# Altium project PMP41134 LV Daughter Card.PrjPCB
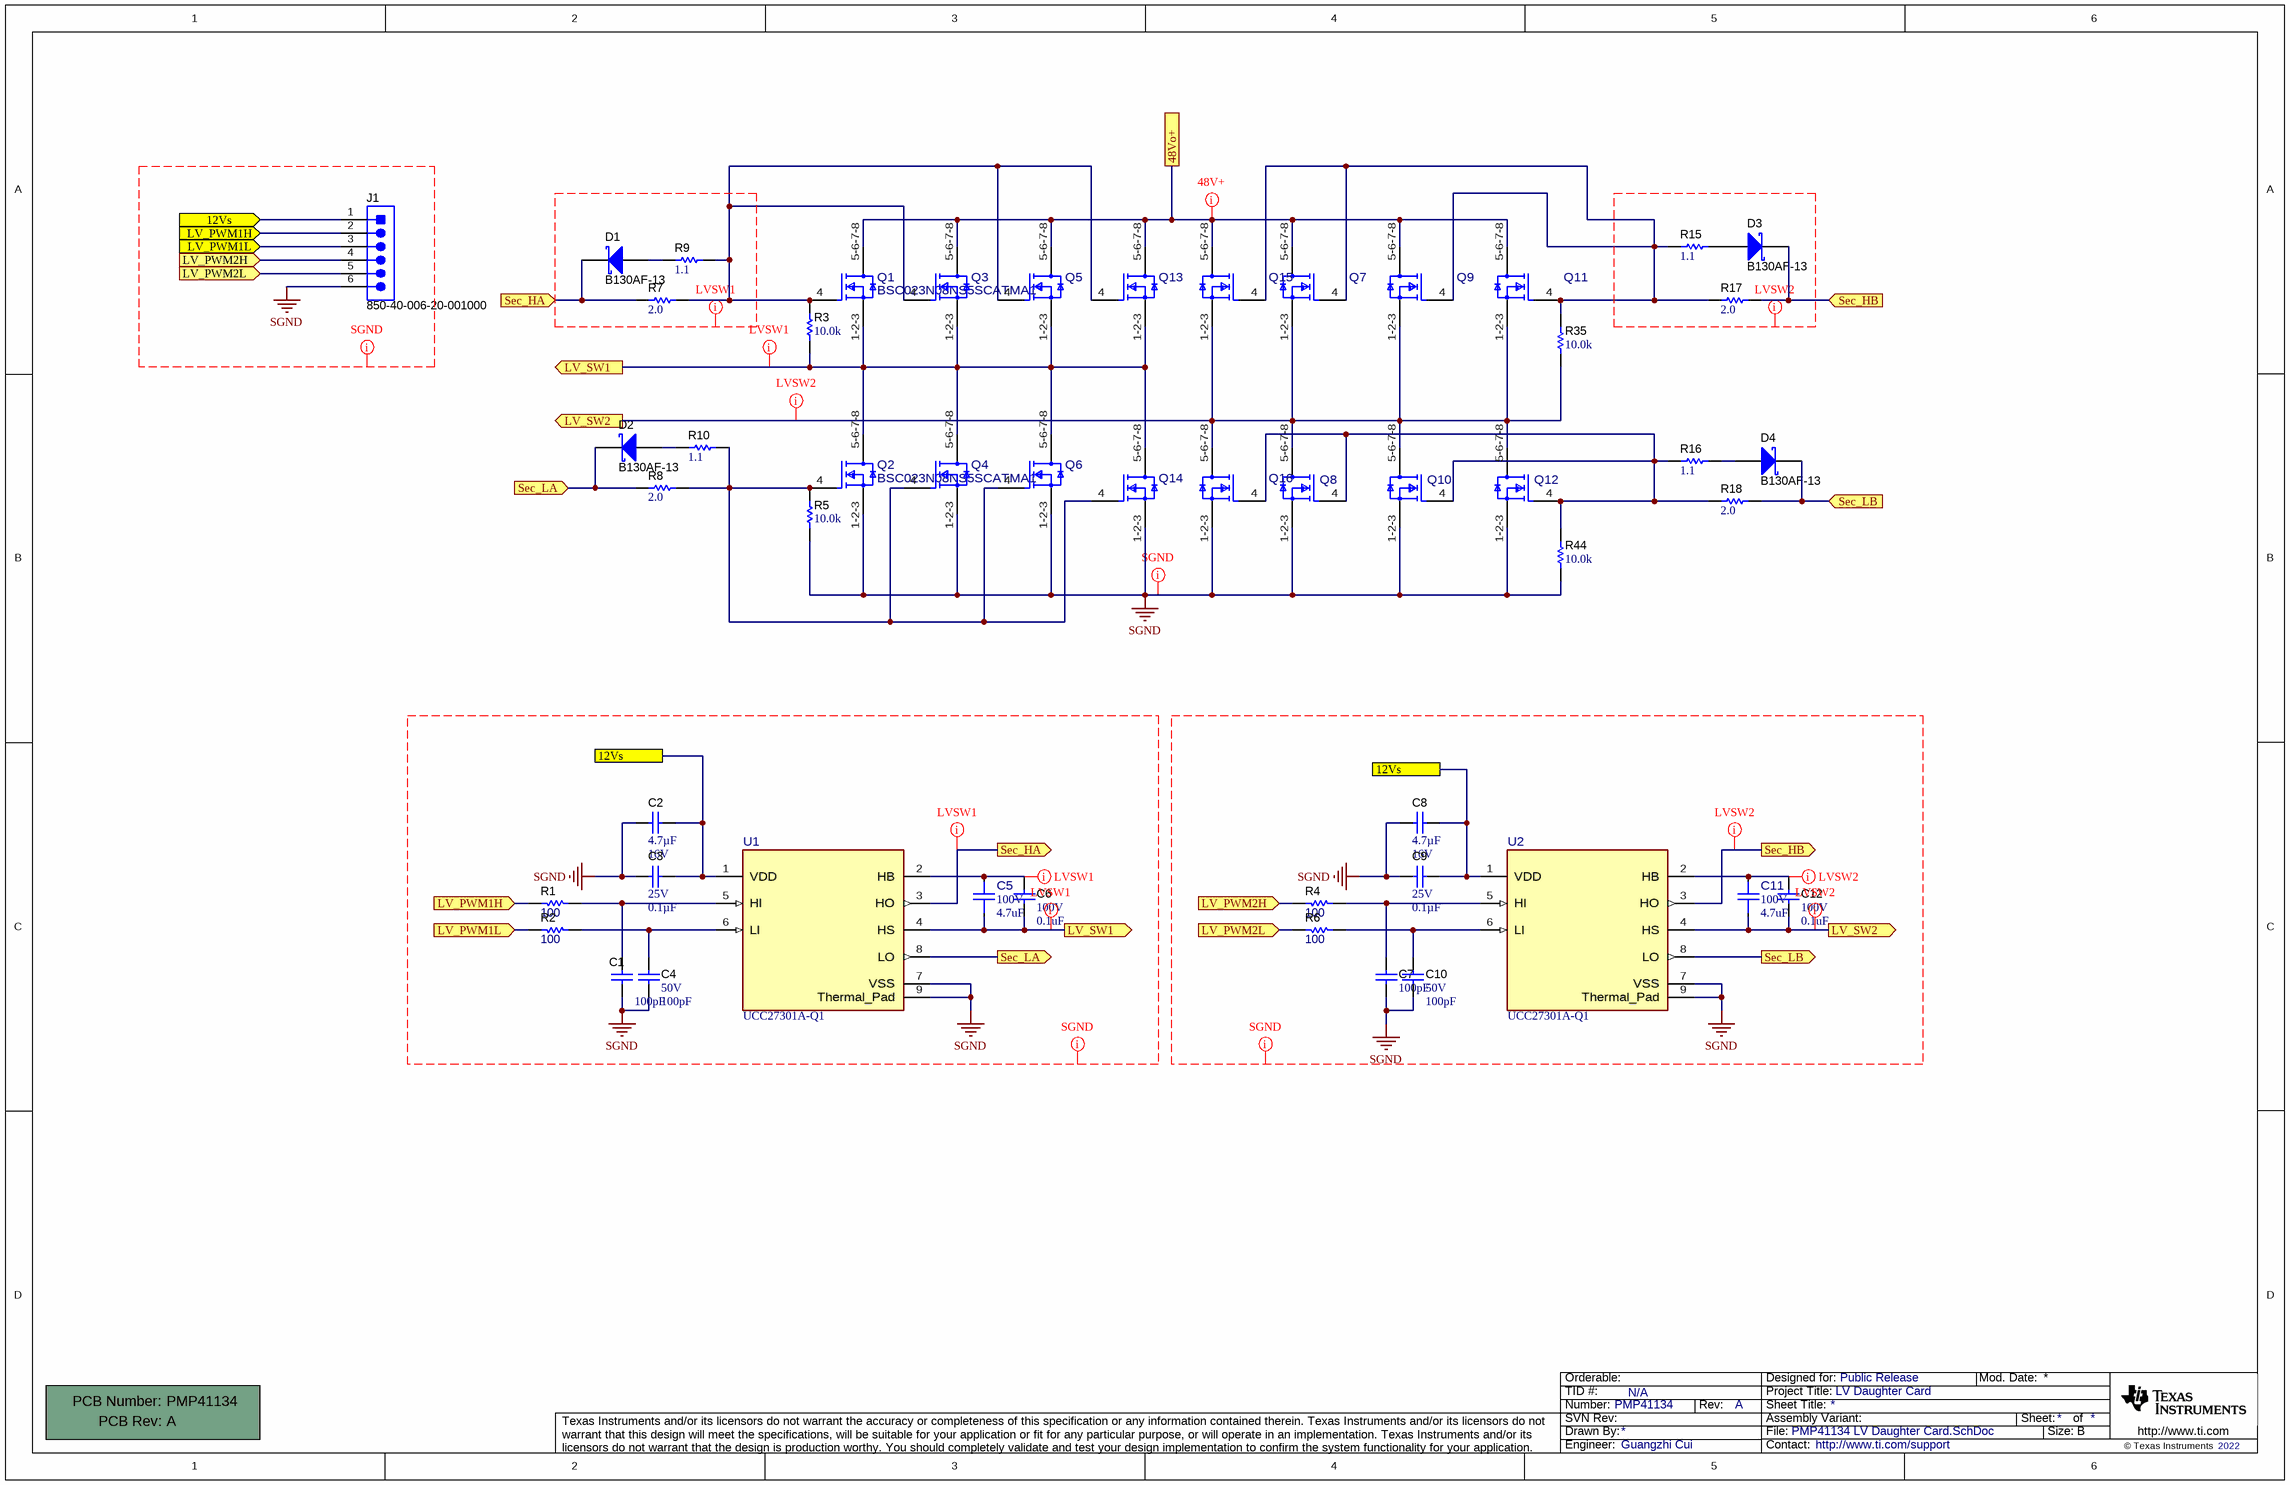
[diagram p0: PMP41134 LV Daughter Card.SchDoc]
CopyrightYear: 2022; PCB_Layout: Guangzhi Cui; PCB_Rev: A; PRJ_Customer: Public Release; PRJ_Engineer: Guangzhi Cui; PRJ_Number: PMP41134; PRJ_Title: LV Daughter Card; SCH_Rev: A; TechSupport: http://www.ti.com/support; TID: N/A
1 sheet, 52 parts. Net scope: flat (ports and power ports of the same name join across sheets).
Board file: PMP41134 LV_Si.PcbDoc

## Sheet PMP41134 LV Daughter Card.SchDoc
size 431 x 279 mm; PageSetup: Record=PageOptions¦CenterHorizontal=True¦CenterVertical=True¦PrintScale=1.00¦XCorrection=1.00¦YCorrection=1.00¦PrintKind=0¦BorderSize=5000000¦LeftOffset=0¦BottomOffset=0¦Orientation=2¦PaperLength=1000¦PaperWidth=1000¦Scale=100¦PaperSource=15¦PrintQuality=600¦MediaType=1¦DitherType=10¦PaperKind=Letter¦PrintScaleMode=1

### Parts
!PCB1  Printed Circuit Board  (value not drawn)  (mechanical)
C1  ValueDisplayed: 100pF  [0402]  (hidden comment: CC0402JRNPO9BN101)
C2  Cap_F: 4.7µF  VDC_V: 16V  [0603]  (hidden comment: GRM188Z71C475KE21D)
C3  VDC_V: 25V  ValueDisplayed: 0.1µF  [0402]  (hidden comment: CGA2B3X7R1E104K050BB)
C4  VDC_V: 50V  ValueDisplayed: 100pF  [0402]  (hidden comment: CC0402JRNPO9BN101)
C5  VDC_V: 100V  ValueDisplayed: 4.7uF  [FP-GRM31CC72A475KE11L_1206-MFG]  (hidden comment: GRM31CC72A475KE11L)
C6  VDC_V: 100V  ValueDisplayed: 0.1uF  [0402]  (hidden comment: GRM155R62A104KE14D)
C7  ValueDisplayed: 100pF  [0402]  (hidden comment: CC0402JRNPO9BN101)
C8  Cap_F: 4.7µF  VDC_V: 16V  [0603]  (hidden comment: GRM188Z71C475KE21D)
C9  VDC_V: 25V  ValueDisplayed: 0.1µF  [0402]  (hidden comment: CGA2B3X7R1E104K050BB)
C10  VDC_V: 50V  ValueDisplayed: 100pF  [0402]  (hidden comment: CC0402JRNPO9BN101)
C11  VDC_V: 100V  ValueDisplayed: 4.7uF  [FP-GRM31CC72A475KE11L_1206-MFG]  (hidden comment: GRM31CC72A475KE11L)
C12  VDC_V: 100V  ValueDisplayed: 0.1uF  [0402]  (hidden comment: GRM155R62A104KE14D)
D1  B130AF-13  [SMAF]
D2  B130AF-13  [SMAF]
D3  B130AF-13  [SMAF]
D4  B130AF-13  [SMAF]
J1  850-40-006-20-001000  [Mill-Max_850-40-006-20-001000]
Q1  BSC023N08NS5SCATMA1  [FP-BSC023N08NS5SCATMA1_WSON8-MFG]
Q2  BSC023N08NS5SCATMA1  [FP-BSC023N08NS5SCATMA1_WSON8-MFG]
Q3  BSC023N08NS5SCATMA1  [FP-BSC023N08NS5SCATMA1_WSON8-MFG]  (value not drawn)
Q4  BSC023N08NS5SCATMA1  [FP-BSC023N08NS5SCATMA1_WSON8-MFG]  (value not drawn)
Q5  BSC023N08NS5SCATMA1  [FP-BSC023N08NS5SCATMA1_WSON8-MFG]  (value not drawn)
Q6  BSC023N08NS5SCATMA1  [FP-BSC023N08NS5SCATMA1_WSON8-MFG]  (value not drawn)
Q7  BSC023N08NS5SCATMA1  [FP-BSC023N08NS5SCATMA1_WSON8-MFG]  (value not drawn)
Q8  BSC023N08NS5SCATMA1  [FP-BSC023N08NS5SCATMA1_WSON8-MFG]  (value not drawn)
Q9  BSC023N08NS5SCATMA1  [FP-BSC023N08NS5SCATMA1_WSON8-MFG]  (value not drawn)
Q10  BSC023N08NS5SCATMA1  [FP-BSC023N08NS5SCATMA1_WSON8-MFG]  (value not drawn)
Q11  BSC023N08NS5SCATMA1  [FP-BSC023N08NS5SCATMA1_WSON8-MFG]  (value not drawn)
Q12  BSC023N08NS5SCATMA1  [FP-BSC023N08NS5SCATMA1_WSON8-MFG]  (value not drawn)
Q13  BSC023N08NS5SCATMA1  [FP-BSC023N08NS5SCATMA1_WSON8-MFG]  (value not drawn)
Q14  BSC023N08NS5SCATMA1  [FP-BSC023N08NS5SCATMA1_WSON8-MFG]  (value not drawn)
Q15  BSC023N08NS5SCATMA1  [FP-BSC023N08NS5SCATMA1_WSON8-MFG]  (value not drawn)
Q16  BSC023N08NS5SCATMA1  [FP-BSC023N08NS5SCATMA1_WSON8-MFG]  (value not drawn)
R1  ValueDisplayed: 100  [0603]  (hidden comment: RC0603FR-07100RL)
R2  ValueDisplayed: 100  [0603]  (hidden comment: RC0603FR-07100RL)
R3  ValueDisplayed: 10.0k  [0402]  (hidden comment: ERJ-2RKF1002X)
R4  ValueDisplayed: 100  [0603]  (hidden comment: RC0603FR-07100RL)
R5  ValueDisplayed: 10.0k  [0402]  (hidden comment: ERJ-2RKF1002X)
R6  ValueDisplayed: 100  [0603]  (hidden comment: RC0603FR-07100RL)
R7  ValueDisplayed: 2.0  [1206]  (hidden comment: CRCW12062R00JNEA)
R8  ValueDisplayed: 2.0  [1206]  (hidden comment: CRCW12062R00JNEA)
R9  ValueDisplayed: 1.1  [1206]  (hidden comment: CRCW12061R10JNEA)
R10  ValueDisplayed: 1.1  [1206]  (hidden comment: CRCW12061R10JNEA)
R15  ValueDisplayed: 1.1  [1206]  (hidden comment: CRCW12061R10JNEA)
R16  ValueDisplayed: 1.1  [1206]  (hidden comment: CRCW12061R10JNEA)
R17  ValueDisplayed: 2.0  [1206]  (hidden comment: CRCW12062R00JNEA)
R18  ValueDisplayed: 2.0  [1206]  (hidden comment: CRCW12062R00JNEA)
R35  ValueDisplayed: 10.0k  [0402]  (hidden comment: ERJ-2RKF1002X)
R44  ValueDisplayed: 10.0k  [0402]  (hidden comment: ERJ-2RKF1002X)
U1  UCC27301A-Q1  [DDA0008A-MFG]
U2  UCC27301A-Q1  [DDA0008A-MFG]

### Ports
12Vs, 12Vs (in), 48Vo+, LV_PWM1H (in), LV_PWM1L (in), LV_PWM2H (in), LV_PWM2L (in), LV_SW1 (out), LV_SW2 (out), Sec_HA (in), Sec_HA (out), Sec_HB (in), Sec_HB (out), Sec_LA (in), Sec_LA (out), Sec_LB (in), Sec_LB (out)

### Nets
SGND: C1.2 C2.1 C3.1 C4.2 C7.2 C8.1 C9.1 C10.2 J1.6 Q2.1-2-3(Source) Q4.1-2-3(Source) Q6.1-2-3(Source) Q8.1-2-3(Source) Q10.1-2-3(Source) Q12.1-2-3(Source) Q14.1-2-3(Source) Q16.1-2-3(Source) R5.1 R44.1 U1.7(VSS) U1.9(Thermal_Pad) U2.7(VSS) U2.9(Thermal_Pad)
12Vs: C2.2 C3.2 C8.2 C9.2 J1.1 U1.1(VDD) U2.1(VDD) ; port 12Vs
48Vo+: Q1.5-6-7-8(Drain) Q3.5-6-7-8(Drain) Q5.5-6-7-8(Drain) Q7.5-6-7-8(Drain) Q9.5-6-7-8(Drain) Q11.5-6-7-8(Drain) Q13.5-6-7-8(Drain) Q15.5-6-7-8(Drain) ; port 48Vo+
LV_PWM1H: J1.2 R1.1 ; port LV_PWM1H
LV_PWM1L: J1.3 R2.1 ; port LV_PWM1L
LV_PWM2H: J1.4 R4.1 ; port LV_PWM2H
LV_PWM2L: J1.5 R6.1 ; port LV_PWM2L
LV_SW1: C5.1 C6.2 Q1.1-2-3(Source) Q2.5-6-7-8(Drain) Q3.1-2-3(Source) Q4.5-6-7-8(Drain) Q5.1-2-3(Source) Q6.5-6-7-8(Drain) Q13.1-2-3(Source) Q14.5-6-7-8(Drain) R3.1 U1.4(HS) ; port LV_SW1
LV_SW2: C11.1 C12.2 Q7.1-2-3(Source) Q8.5-6-7-8(Drain) Q9.1-2-3(Source) Q10.5-6-7-8(Drain) Q11.1-2-3(Source) Q12.5-6-7-8(Drain) Q15.1-2-3(Source) Q16.5-6-7-8(Drain) R35.1 U2.4(HS) ; port LV_SW2
Sec_HA: D1.1(K) R7.1 U1.3(HO) ; port Sec_HA
Sec_HB: D3.1(K) R17.2 U2.3(HO) ; port Sec_HB
Sec_LA: D2.1(K) R8.1 U1.8(LO) ; port Sec_LA
Sec_LB: D4.1(K) R18.2 U2.8(LO) ; port Sec_LB
NetC1_1: C1.1 R1.2 U1.5(HI)
NetC4_1: C4.1 R2.2 U1.6(LI)
NetC5_2: C5.2 C6.1 U1.2(HB)
NetC7_1: C7.1 R4.2 U2.5(HI)
NetC10_1: C10.1 R6.2 U2.6(LI)
NetC11_2: C11.2 C12.1 U2.2(HB)
NetD1_2: D1.2(A) R9.1
NetD2_2: D2.2(A) R10.1
NetD3_2: D3.2(A) R15.2
NetD4_2: D4.2(A) R16.2
NetQ1_4: Q1.4(Gate) Q3.4(Gate) Q5.4(Gate) Q13.4(Gate) R3.2 R7.2 R9.2
NetQ2_4: Q2.4(Gate) Q4.4(Gate) Q6.4(Gate) Q14.4(Gate) R5.2 R8.2 R10.2
NetQ7_4: Q7.4(Gate) Q9.4(Gate) Q11.4(Gate) Q15.4(Gate) R15.1 R17.1 R35.2
NetQ8_4: Q8.4(Gate) Q10.4(Gate) Q12.4(Gate) Q16.4(Gate) R16.1 R18.1 R44.2

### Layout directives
net class 48V+: 48Vo+
net class SGND: SGND
net class LVSW1: (no net found under the mark), LV_SW1, NetC5_2, Sec_HA
net class LVSW2: (no net found under the mark), LV_SW2, NetC11_2, Sec_HB

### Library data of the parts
!PCB1 = CMP-0003618-2: Manufacturer: Any; PartNumber: PMP41134
C1 C7 = CMP-0006303-2: CAP, CERM, 100 pF, 50 V, +/- 5%, C0G/NP0, 0402; Manufacturer: Yageo America; TaMin_C: -55°C; Polarized: N; SizeAreaWB_mm2: 3; Value1: Unknown; U/M: EA; Value: 100pF; TaMax_C: 125°C; SizeZ_mm: 0.6; SizeX_mm: 1; SizeY_mm: 0.5; Value2: 50V; AEC Category: Q200
C2 C8 = CMP-0064936-4: CAP, CERM, 4.7 uF, 16 V,+/- 10%, X7R, 0603; Manufacturer: MuRata; TaMin_C: -55°C; Polarized: N; SizeAreaWB_mm2: 4.68; Value1: Unknown; U/M: EA; Value: 4.7uF; TaMax_C: 125°C; SizeZ_mm: 1; SizeX_mm: 1.6; SizeY_mm: 0.8; SizeArea_mm2: 1.28; AEC Category: Q200
C3 C9 = CMP-0080610-1: CAP, CERM, 0.1 µF, 25 V,+/- 10%, X7R, AEC-Q200 Grade 1, 0402; Manufacturer: TDK; TaMin_C: -55°C; Polarized: N; SizeAreaWB_mm2: 3; U/M: EA; Value: 0.1uF; TaMax_C: 125°C; SizeZ_mm: 0.6; SizeX_mm: 1; SizeY_mm: 0.5; AEC Qualified: Y; Cap_F: 100nF; AEC Category: Q200
C4 C10 = CMP-0006303-2: CAP, CERM, 100 pF, 50 V, +/- 5%, C0G/NP0, 0402; Manufacturer: Yageo America; TaMin_C: -55°C; Polarized: N; SizeAreaWB_mm2: 3; Value1: Unknown; U/M: EA; Value: 100pF; TaMax_C: 125°C; SizeZ_mm: 0.6; SizeX_mm: 1; SizeY_mm: 0.5; AEC Category: Q200
C5 C11 = CMP-0089881-1: 4.7µF ±10% 100V Ceramic Capacitor X7S 1206 (3216 Metric); Manufacturer: Murata; TempCo: 22%; AEC Qualified: No; SizeZ_mm: 1.9mm
C6 C12 = CMP-0006618-1: CAP, CERM, 0.1 uF, 100 V, +/- 10%, X5R, 0402; Manufacturer: MuRata; TaMin_C: -55°C; Polarized: N; SizeAreaWB_mm2: 3; Value1: Unknown; U/M: EA; Value: 0.1uF; TaMax_C: 85°C; SizeZ_mm: 0.6; SizeX_mm: 1; SizeY_mm: 0.5; Cap_F: 100nF; AEC Category: Q200
D1-D4 = CMP-0085599-1: Diode, Schottky, 30 V, 1 A, SMAF; Manufacturer: Diodes Inc.; SizeArea_mm2: 11.75; Io_A: 1A; AEC Category: Q101; SizeZ_mm: 1; SizeY_mm: 2.5; TJmax_C: 150°C; Vf_V: 500mV; RJC_CperW: 45; SizeX_mm: 4.7; AEC Qualified: N; Value2: 0.5V; Value: 30V; SizeAreaWB_mm2: 19.95
J1 = CMP-0055095-1: Header, 1.27 mm, 6x1, Tin, R/A, TH; Manufacturer: Mill-Max; CNHeader: TRUE; Shrouded: N; Gender: Male; Row_Count: 1; Pitch_mm: 1.27; CT: FALSE
Q1-Q16 = CMP-0123078-1: N-Channel 80 V 202A (Tc) 188W (Tc) Surface Mount PG-WSON-8-2; Manufacturer: Infineon; AEC Qualified: No; IdsMax_A: 26A; QgTyp_nC: 78nC @ 10V; Rdson45_ohm: 1.94m; SizeZ_mm: 0.75mm; VdsMax_V: 1.1V; Vgs_V: 20V; ChMode: False; Drain To Source Breakdown Voltage: 80V; Input Capacitance At Vds: 5200pF @ 40V; Number Of Channels: 1; Power_W: 3W; Pulse Drain Current: 808A; Reverse Recovery Charge: 92nC; Reverse Recovery Time: 56ns; Rthja Max: 50K/W; Standoff Height: 0mm; Threshold Vgs Max: 3.8V; Threshold Vgs Min: 2.2V; TJmax_C: +175°C; Transconductance: 120S; Turn Off Delay Time: 40ns; Turn On Delay Time: 21ns; Typ Forward Diode Voltage: 0.84V
R1 R2 R4 R6 = CMP-0022736-4: RES, 100, 1%, 0.1 W, 0603; Manufacturer: Yageo; Power_W: 100mW; TempCo: 100 ppm/C; Value_Code: 100R; Value: 100; EIA_Code: E96; SizeX_mm: 1.6; SizeY_mm: 0.8; SizeZ_mm: 1; Value2: 0.1W; SizeArea_mm2: 1.28; AEC Qualified: N; VDC_V: 75V; AEC Category: Q200; SizeAreaWB_mm2: 4.68
R3 R5 R35 R44 = CMP-0026658-1: RES, 10.0 k, 1%, 0.1 W, 0402; Manufacturer: Panasonic; Power_W: 100mW; TempCo: 100 ppm/C; Value_Code: 10k0; U/M: EA; Value: 10.0k; EIA_Code: E96; Res_ohm: 10k; SizeX_mm: 1; SizeY_mm: 0.5; SizeZ_mm: 0.6; Value2: 0.1W; VDC_V: 50V; AEC Category: Q200
R7 R8 R17 R18 = CMP-0018648-3: RES, 2.0, 5%, 0.25 W, AEC-Q200 Grade 0, 1206; Manufacturer: Vishay-Dale; Power_W: 250mW; TempCo: 200 ppm/C; Value_Code: 2R00; Value: 2.0; EIA_Code: E24; Res_ohm: 2; SizeX_mm: 3.2; SizeY_mm: 1.6; SizeZ_mm: 1.35; Value2: 0.25W; SizeArea_mm2: 5.12; AEC Qualified: Y; VDC_V: 200V; AEC Category: Q200; AEC Grade: 0
R9 R10 R15 R16 = CMP-0018618-3: RES, 1.1, 5%, 0.25 W, AEC-Q200 Grade 0, 1206; Manufacturer: Vishay-Dale; Power_W: 250mW; TempCo: 200 ppm/C; Value_Code: 1R10; Value: 1.1; EIA_Code: E24; SizeX_mm: 3.2; SizeY_mm: 1.6; SizeZ_mm: 1.35; Value2: 0.25W; SizeArea_mm2: 5.12; AEC Qualified: Y; VDC_V: 200V; AEC Category: Q200; AEC Grade: 0
U1 U2 = CMP-0123128-1: Automotive 120V, 3.7A/4.5A Half-Bridge Driver with 8V UVLO, Interlock and Enable; Manufacturer: Texas Instruments; SizeZ_mm: 1.7mm; AEC Qualified: Yes; AEC Grade: Grade 1; Fall Time: 5.5ns; Max Supply Voltage: 17V; Nominal Supply Current: 0.11-1.4mA; Number Of Drivers: 2; Propagation Delay: 20ns; Rise Time: 7.2ns; Standoff Height: 0mm; TaMax_C: +125°C; TaMin_C: -40°C; TJmax_C: +150°C

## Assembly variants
Variant of PMP23126.1 GaN Daughter Card: not fitted C18 C21 D3 R8 R9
